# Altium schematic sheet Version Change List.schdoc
size 418 x 190 mm
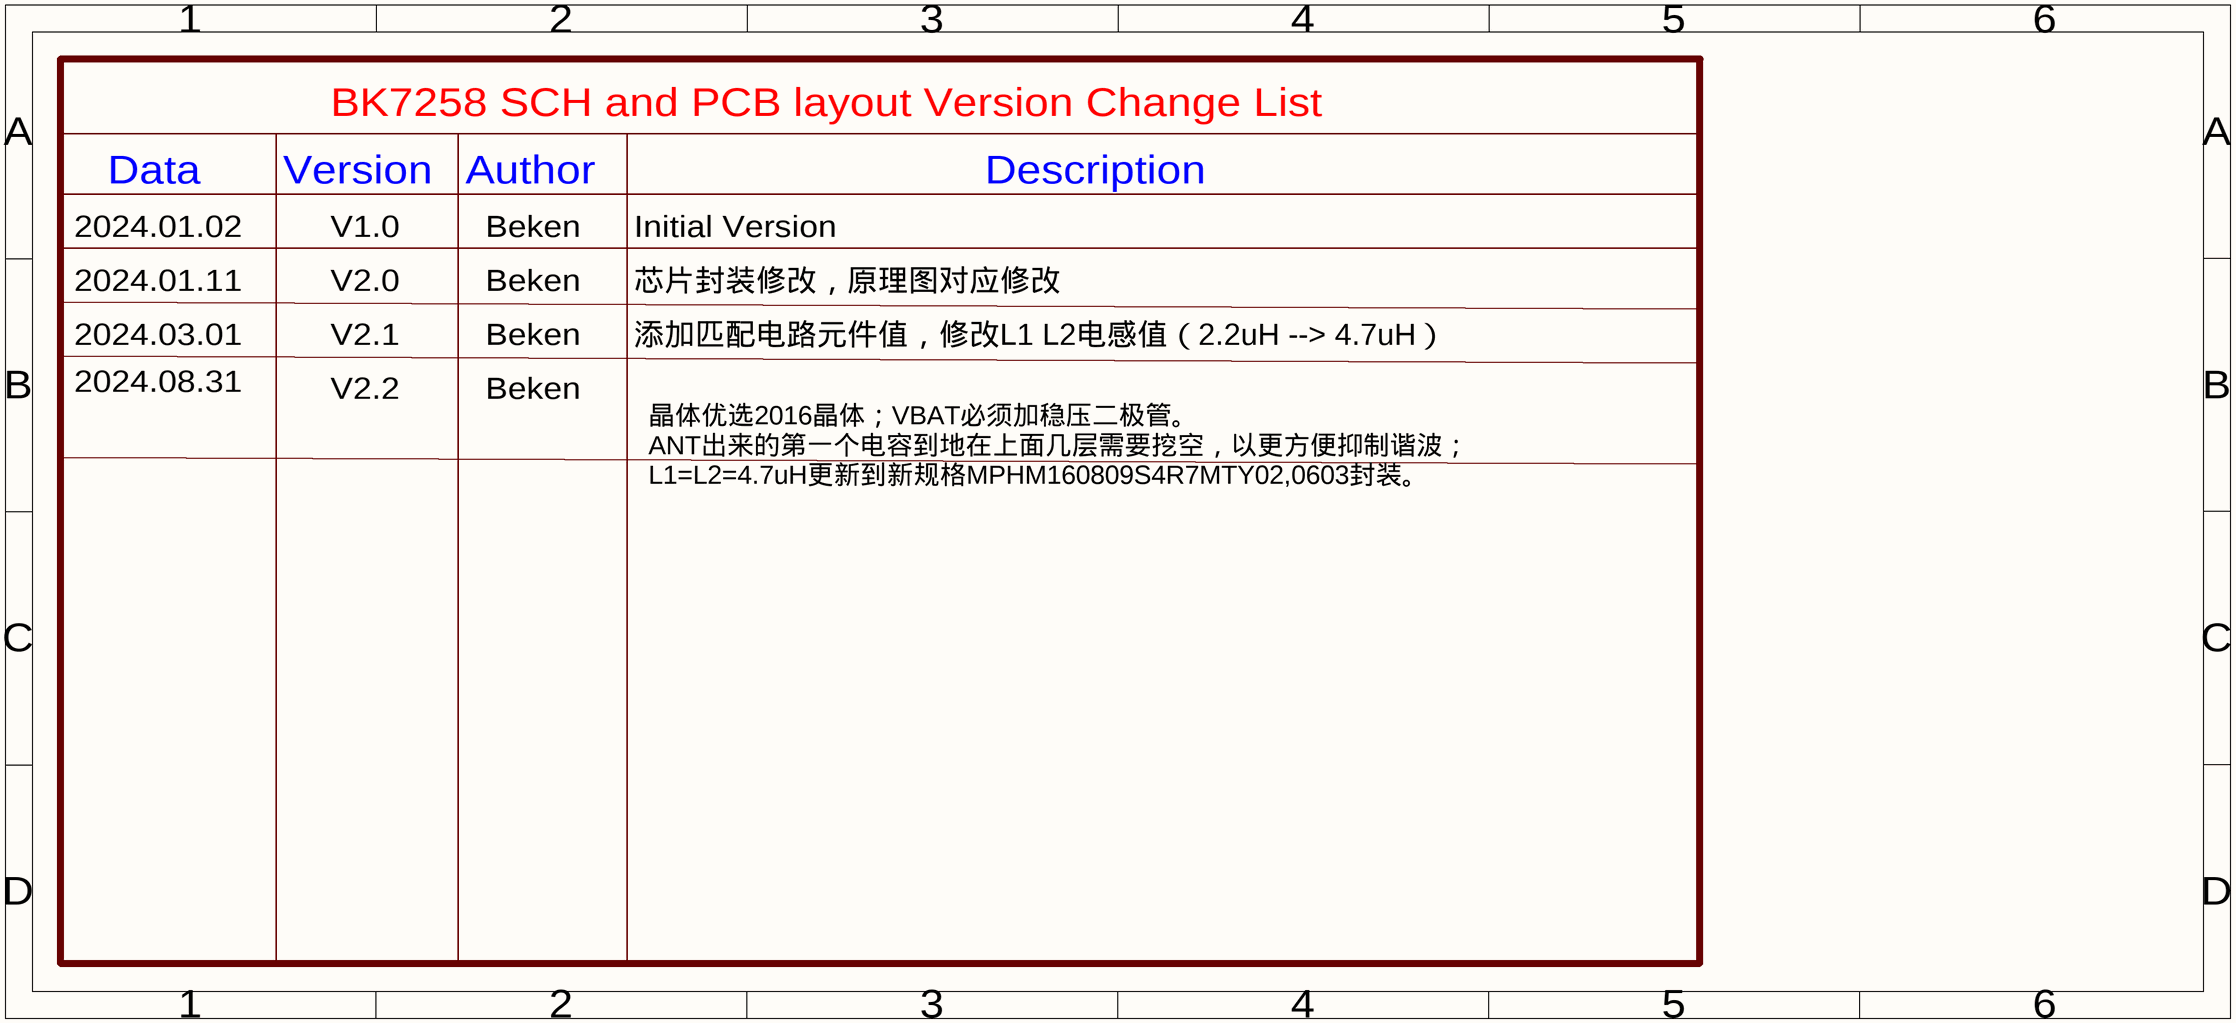
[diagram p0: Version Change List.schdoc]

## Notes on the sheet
- BK7258 SCH and PCB layout Version Change List
- Data
- Version
- Author
- Description
- 2024.01.02
- 2024.01.11
- V1.0
- V2.0
- Beken
- Initial Version
- 芯片封装修改，原理图对应修改
- 2024.03.01
- V2.1
- 添加匹配电路元件值，修改L1 L2电感值（2.2uH --> 4.7uH）
- 2024.08.31
- V2.2
- 晶体优选2016晶体；VBAT必须加稳压二极管。
  ANT出来的第一个电容到地在上面几层需要挖空，以更方便抑制谐波；
  L1=L2=4.7uH更新到新规格MPHM160809S4R7MTY02,0603封装。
